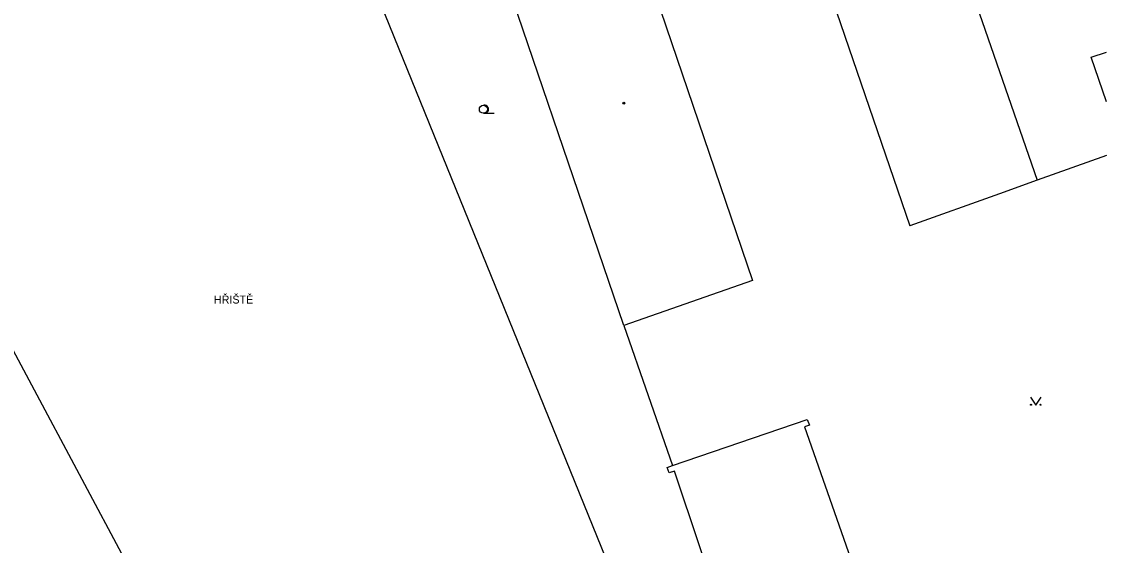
# Model space of a CAD drawing. Extents: x -600391 to -599491, y -1160176 to -1159402.
# Drawn here: x -599592.4 to -599490.8, y -1159748.8 to -1159699.8 of the extents above; entities that cross this region are included whole.
import ezdxf

# ---------------------------------------------------------------- set-up
doc = ezdxf.new("R2010")
doc.units = 0
for name, color, linetype in [('Level 11', 7, 'Continuous'), ('Level 36', 7, 'Continuous'), ('Level 39', 7, 'Continuous'), ('Level 41', 7, 'Continuous'), ('Level 5', 7, 'Continuous'), ('Level 51', 7, 'Continuous')]:
    doc.layers.add(name, color=color, linetype=linetype)

msp = doc.modelspace()

# ---------------------------------------------------------------- linework, layer by layer
at = {"layer": 'Level 11'}
for points in [[(-599533.11, -1159761.26), (-599564.52, -1159683.85), (-599576.16, -1159655.18)], [(-599569.11, -1159775.68), (-599618.27, -1159683.56)]]:
    msp.add_lwpolyline(points, dxfattribs=at)
at = {"layer": 'Level 36'}
msp.add_line((-599549.14, -1159708.34), (-599548.14, -1159708.34), dxfattribs=at)
msp.add_lwpolyline([(-599497.88, -1159734.96), (-599497.38, -1159735.71), (-599496.88, -1159734.96)], dxfattribs=at)
for centre, radius in [((-599549.14, -1159707.97), 0.375), ((-599497.83, -1159735.66), 0.05), ((-599496.93, -1159735.66), 0.05)]:
    msp.add_circle(centre, radius, dxfattribs=at)
msp.add_arc((-599549.02, -1159707.97), 0.375, 260.4059, 99.5941, dxfattribs=at)
at = {"layer": 'Level 39'}
for radius in [0.09, 0.0398]:
    msp.add_circle((-599535.97, -1159707.41), radius, dxfattribs=at)
at = {"layer": 'Level 5'}
for p, q in [((-599492.19, -1159703.1), (-599490.77, -1159702.61)), ((-599490.77, -1159707.29), (-599492.19, -1159703.1))]:
    msp.add_line(p, q, dxfattribs=at)
for points in [[(-599537.6, -1159683.79), (-599523.93, -1159724.01)], [(-599535.97, -1159728.23), (-599549.69, -1159687.96)], [(-599523.93, -1159724.01), (-599535.97, -1159728.23)], [(-599531.41, -1159741.34), (-599518.8, -1159737.05)], [(-599518.59, -1159737.57), (-599519.05, -1159737.74)], [(-599519.05, -1159737.74), (-599508.93, -1159766.62)], [(-599518.8, -1159737.05), (-599518.59, -1159737.57)], [(-599531.92, -1159741.55), (-599531.41, -1159741.34)], [(-599531.74, -1159742.03), (-599531.92, -1159741.55)], [(-599531.22, -1159741.9), (-599531.74, -1159742.03)], [(-599526.51, -1159755.98), (-599531.22, -1159741.9)]]:
    msp.add_lwpolyline(points, dxfattribs=at)
at = {"layer": 'Level 51'}
msp.add_line((-599490.77, -1159712.29), (-599497.24, -1159714.63), dxfattribs=at)
for points in [[(-599511.1, -1159674.67), (-599497.24, -1159714.63)], [(-599522.91, -1159678.77), (-599509.17, -1159718.89)], [(-599497.24, -1159714.63), (-599500.78, -1159715.91)], [(-599500.78, -1159715.91), (-599509.17, -1159718.89)], [(-599535.97, -1159728.23), (-599531.41, -1159741.34)]]:
    msp.add_lwpolyline(points, dxfattribs=at)

# ---------------------------------------------------------------- texts
at = {"layer": 'Level 41'}
msp.add_text('HŘIŠTĚ', height=0.75, dxfattribs=at).set_placement((-599574.38, -1159726.18))

doc.saveas('drawing.dxf')
